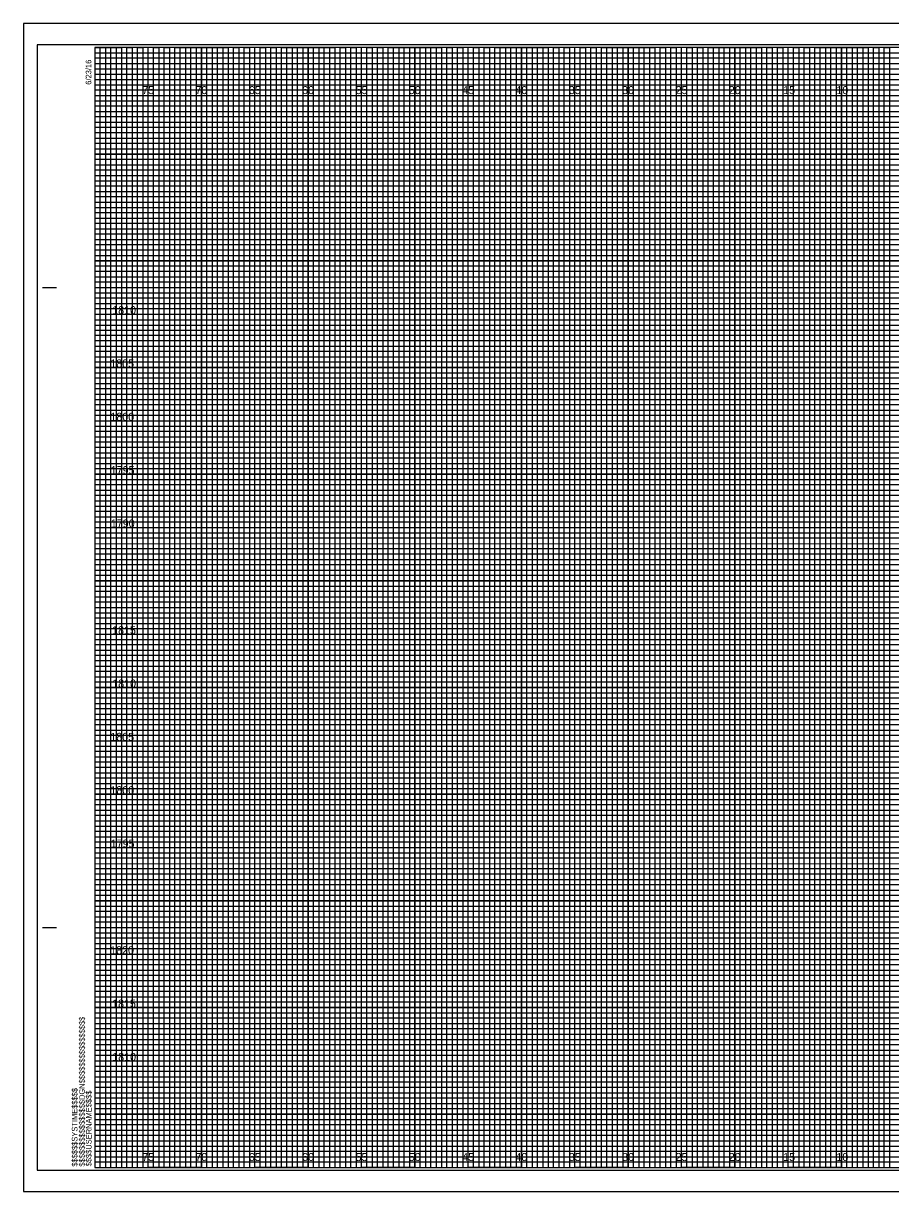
# Model space of a CAD drawing. Extents: x -7 to 162, y -2 to 327.
# Drawn here: x -6.7 to 74.6, y -2.3 to 107.3 of the extents above; entities that cross this region are included whole.
import ezdxf

# ---------------------------------------------------------------- set-up
doc = ezdxf.new("R2010")
doc.units = 0
for name, color, linetype in [('Raster_Level_0', 7, 'Continuous'), ('Scratch_Level_3', 7, 'Continuous'), ('Sheet Cross Section CELL', 7, 'Continuous'), ('Sheet Cross Section Grid Major CELL', 7, 'Continuous'), ('Sheet Cross Section Grid Middle CELL', 7, 'Continuous'), ('Sheet Cross Section Grid Minor 1 CELL', 7, 'Continuous'), ('Sheet Cross Section Grid Minor 2 CELL', 7, 'Continuous'), ('Sheet Cutting Line CELL', 7, 'Continuous'), ('Sheet DOT Grid CELL', 7, 'Continuous'), ('Sheet Plot Border Inside CELL', 7, 'Continuous'), ('Sheet Plot Border Outside CELL', 7, 'Continuous')]:
    doc.layers.add(name, color=color, linetype=linetype)

msp = doc.modelspace()

# ---------------------------------------------------------------- linework, layer by layer
at = {"layer": 'Sheet Cross Section CELL'}
for p, q in [((-4.9, 82.5), (-3.65, 82.5)), ((-4.85, 82.5), (-3.6, 82.5)), ((-4.9, 22.5), (-3.65, 22.5)), ((-4.85, 22.5), (-3.6, 22.5)), ((0, 0), (0, 0)), ((0, 0), (0, 0)), ((0, 0), (0, 0)), ((0, 0), (0, 0)), ((0, 0), (0, 0)), ((0, 0), (0, 0)), ((0, 0), (0, 0))]:
    msp.add_line(p, q, dxfattribs=at)
msp.add_lwpolyline([(160, 105), (0, 105), (0, 0), (160, 0)], close=True, dxfattribs=at)
at = {"layer": 'Sheet Cross Section Grid Major CELL'}
for p, q in [((5, 105), (0, 105)), ((5, 0), (5, 105)), ((15, 105), (10, 105)), ((10, 105), (10, 0)), ((15, 0), (15, 105)), ((25, 105), (20, 105)), ((20, 105), (20, 0)), ((25, 0), (25, 105)), ((35, 105), (30, 105)), ((30, 105), (30, 0)), ((35, 0), (35, 105)), ((45, 105), (40, 105)), ((40, 105), (40, 0)), ((45, 0), (45, 105)), ((55, 105), (50, 105)), ((50, 105), (50, 0)), ((55, 0), (55, 105)), ((65, 105), (60, 105)), ((60, 105), (60, 0)), ((65, 0), (65, 105)), ((75, 105), (70, 105)), ((70, 105), (70, 0)), ((10, 0), (5, 0)), ((20, 0), (15, 0)), ((30, 0), (25, 0)), ((40, 0), (35, 0)), ((50, 0), (45, 0)), ((60, 0), (55, 0)), ((70, 0), (65, 0))]:
    msp.add_line(p, q, dxfattribs=at)
for points in [[(0, 100), (160, 100), (160, 95), (0, 95)], [(0, 90), (160, 90), (160, 85), (0, 85)], [(0, 80), (160, 80), (160, 75), (0, 75)], [(0, 70), (160, 70), (160, 65), (0, 65)], [(0, 60), (160, 60), (160, 55), (0, 55)], [(0, 50), (160, 50), (160, 45), (0, 45)], [(0, 40), (160, 40), (160, 35), (0, 35)], [(0, 30), (160, 30), (160, 25), (0, 25)], [(0, 20), (160, 20), (160, 15), (0, 15)], [(0, 10), (160, 10), (160, 5), (0, 5)]]:
    msp.add_lwpolyline(points, dxfattribs=at)
at = {"layer": 'Sheet Cross Section Grid Middle CELL'}
for points in [[(0, 105), (2.5, 105), (2.5, 0), (7.5, 0), (7.5, 105), (12.5, 105), (12.5, 0), (17.5, 0), (17.5, 105), (22.5, 105), (22.5, 0), (27.5, 0), (27.5, 105), (32.5, 105), (32.5, 0), (37.5, 0), (37.5, 105), (42.5, 105), (42.5, 0), (47.5, 0), (47.5, 105), (52.5, 105), (52.5, 0), (57.5, 0), (57.5, 105), (62.5, 105), (62.5, 0), (67.5, 0), (67.5, 105), (72.5, 105), (72.5, 0), (77.5, 0)], [(0, 102.5), (137.5, 102.5)], [(0, 92.5), (160, 92.5), (160, 97.5), (0, 97.5)], [(0, 82.5), (160, 82.5), (160, 87.5), (0, 87.5)], [(0, 72.5), (160, 72.5), (160, 77.5), (0, 77.5)], [(0, 62.5), (160, 62.5), (160, 67.5), (0, 67.5)], [(0, 52.5), (160, 52.5), (160, 57.5), (0, 57.5)], [(0, 42.5), (160, 42.5), (160, 47.5), (0, 47.5)], [(0, 32.5), (160, 32.5), (160, 37.5), (0, 37.5)], [(0, 22.5), (160, 22.5), (160, 27.5), (0, 27.5)], [(0, 12.5), (160, 12.5), (160, 17.5), (0, 17.5)], [(0, 2.5), (160, 2.5), (160, 7.5), (0, 7.5)]]:
    msp.add_lwpolyline(points, dxfattribs=at)
at = {"layer": 'Sheet Cross Section Grid Minor 1 CELL'}
for p, q in [((0, 104.5), (130, 104.5)), ((130, 103.99), (0, 103.99)), ((0, 103.99), (0, 103.5)), ((0, 103.5), (130, 103.5)), ((130, 102.95), (0, 102.95)), ((0, 102.95), (0, 102)), ((0, 102), (160, 102))]:
    msp.add_line(p, q, dxfattribs=at)
for points in [[(0, 101.5), (135, 101.5), (160, 101.5), (160, 101), (0, 101)], [(0, 100.5), (160, 100.5), (160, 99.5), (0, 99.5)], [(0, 99), (160, 99), (160, 98.5), (0, 98.49)], [(0, 98), (160, 98), (160, 97), (0, 97)], [(0, 96.5), (160, 96.5), (160, 96), (0, 96)], [(0, 95.5), (160, 95.5), (160, 94.5), (0, 94.5)], [(0, 94), (160, 94), (160, 93.5), (0, 93.5)], [(0, 93), (160, 93), (160, 92), (0, 92)], [(0, 91.5), (160, 91.5), (160, 91), (0, 91)], [(0, 90.5), (160, 90.5), (160, 89.5), (0, 89.5)], [(0, 89), (160, 89), (160, 88.5), (0, 88.5)], [(0, 88), (160, 88), (160, 86.98), (160, 86.5), (160, 86), (0, 86)], [(0, 87), (160, 87), (160, 86.5), (0, 86.5)], [(0, 85.5), (160, 85.5), (160, 84.5), (0, 84.52)], [(0, 84.52), (160, 84.5), (160, 84), (0, 84)], [(0, 83.5), (160, 83.5), (160, 83), (0, 83)], [(0, 82), (160, 82), (160, 81.5), (0, 81.5)], [(0, 81), (160, 81), (160, 80.5), (0, 80.5)], [(-0.04, 79.45), (160, 79.45), (160, 78.94), (-0.04, 78.94)], [(0, 78.5), (160, 78.5), (160, 78), (0, 78)], [(0, 77), (160, 77), (160, 76.5), (0, 76.5)], [(0, 76), (160, 76), (160, 75.5), (0, 75.5)], [(0, 74.5), (160, 74.5), (160, 74), (0, 74)], [(0, 73.5), (160, 73.5), (160, 73), (0, 73)], [(0, 72), (160, 72), (160, 71.5), (0, 71.5)], [(0, 71), (160, 71), (160, 70.5), (0, 70.5)], [(0, 69.5), (160, 69.5), (160, 68.99), (0, 69)], [(0, 68.5), (160, 68.5), (160, 68), (0, 68)], [(0, 67), (160, 67), (160, 66.5), (0, 66.5)], [(0, 66), (160, 66), (160, 65.5), (0, 65.5)], [(0, 64.5), (160, 64.5), (160, 64), (0, 64)], [(0, 63.5), (160, 63.5), (160, 63), (0, 63)], [(0, 62), (160, 62), (160, 61.5), (0, 61.5)], [(0, 61), (160, 61), (160, 60.5), (0, 60.5)], [(0, 59.5), (160, 59.5), (160, 59), (0, 59)], [(0, 58.5), (160.03, 58.45), (160, 58), (0, 58)], [(0, 57), (160, 57), (160, 56.5), (0, 56.5)], [(0, 56), (160, 56), (160, 55.5), (0, 55.5)], [(0, 54.5), (160, 54.5), (160, 54), (0, 54)], [(0, 53.5), (160, 53.5), (160, 53), (0, 53)], [(0, 52), (160, 52), (160, 51.5), (0, 51.5)], [(0, 51), (160, 51), (160, 50.5), (0, 50.5)], [(0, 49.5), (160, 49.5), (160, 49), (0, 49)], [(0, 48.5), (160, 48.5), (160, 48), (0, 48)], [(0, 47), (160, 47), (160, 46.5), (0, 46.5)], [(0, 46), (160, 46), (160, 45.5), (0, 45.5)], [(0, 44.5), (160, 44.5), (160, 44), (0, 44)], [(0, 43.5), (160, 43.5), (160, 43), (0, 43)], [(0, 42), (160, 42), (160, 41.5), (0, 41.5)], [(0, 41), (160, 41), (160, 40.5), (0, 40.5)], [(0, 39.5), (160, 39.5), (160, 38.99), (0, 39)], [(0, 38.5), (160, 38.5), (160, 38), (0, 38)], [(0, 37), (160, 37), (160, 36.5), (0, 36.5)], [(0, 36), (160, 36), (160, 35.5), (0, 35.5)], [(0, 34.5), (160, 34.5), (160, 34), (0, 34)], [(0, 33.5), (160, 33.5), (160, 33), (0, 33)], [(0, 32), (160, 32), (160, 31.5), (0, 31.5)], [(0, 31), (160, 31), (160, 30.5), (0, 30.5)], [(0, 29.5), (160, 29.5), (160, 29), (0, 29)], [(0, 28.5), (160.03, 28.46), (160, 28), (0, 28)], [(0, 27), (160, 27), (160, 26.5), (0, 26.5)], [(0, 26), (160, 26), (160, 25.5), (0, 25.5)], [(0, 24.5), (160, 24.5), (160, 24), (0, 24)], [(0, 23.5), (160, 23.5), (160, 23), (0, 23)], [(0, 22), (160, 22), (160, 21.5), (0, 21.5)], [(0, 21), (160, 21), (160, 20.5), (0, 20.5)], [(0, 19.5), (160, 19.5), (160, 19), (0, 19)], [(0, 18.5), (160, 18.5), (160, 18), (0, 18)], [(0, 17), (160, 17), (160, 16.5), (0, 16.5)], [(0, 16), (160, 16), (160, 15.5), (0, 15.5)], [(0, 14.5), (160, 14.5), (160, 14), (0, 14)], [(0, 13.5), (160, 13.5), (160, 13), (0, 13)], [(0, 12), (160, 12), (160, 11.5), (0, 11.5)], [(0, 11), (160, 11), (160, 10.5), (0, 10.5)], [(0, 9.5), (160, 9.5), (160, 9), (0, 9)], [(0, 8.5), (160, 8.5), (160, 8), (0, 8)], [(0, 7), (160, 7), (160, 6.5), (0, 6.5)], [(0, 6), (160, 6), (160, 5.5), (0, 5.5)], [(0, 4.5), (160, 4.5), (160, 4), (0, 4)], [(0, 3.5), (160, 3.5), (160, 3), (0, 3)], [(0, 2), (160, 2), (160, 1.5), (0, 1.5)], [(0, 1), (160, 1), (160, 0.5), (0, 0.5)]]:
    msp.add_lwpolyline(points, dxfattribs=at)
at = {"layer": 'Sheet Cross Section Grid Minor 2 CELL'}
for points in [[(0, 0), (0.5, 0), (0.5, 105), (1, 105), (1, 0)], [(1, 0), (1.5, 0), (1.5, 105), (2, 105), (2, 0)], [(2.5, 0), (3, 0), (3, 105), (3.5, 105), (3.5, 0)], [(3.5, 0), (4, 0), (4, 105), (4.5, 105), (4.5, 0)], [(5, 0), (5.5, 0), (5.5, 105), (6, 105), (6, 0)], [(6, 0), (6.5, 0), (6.5, 105), (7, 105), (7, 0)], [(7.5, 0), (8, 0), (8, 105), (8.5, 105), (8.5, 0)], [(8.5, 0), (9, 0), (9, 105), (9.5, 105), (9.5, 0)], [(10, 0), (10.5, 0), (10.5, 105), (11, 105), (11, 0)], [(11, 0), (11.5, 0), (11.5, 105), (12, 105), (12, 0)], [(12.5, 0), (13, 0), (13, 105), (13.5, 105), (13.5, 0)], [(13.5, 0), (14, 0), (14, 105), (14.5, 105), (14.5, 0)], [(15, 0), (15.5, 0), (15.5, 105), (16, 105), (16, 0)], [(16, 0), (16.5, 0), (16.5, 105), (17, 105), (17, 0)], [(17.5, 0), (18, 0), (18, 105), (18.5, 105), (18.5, 0)], [(18.5, 0), (19, 0), (19, 105), (19.5, 105), (19.5, 0)], [(20, 0), (20.5, 0), (20.5, 105), (21, 105), (21, 0)], [(21, 0), (21.5, 0), (21.5, 105), (22, 105), (22, 0)], [(22.5, 0), (23, 0), (23, 105), (23.5, 105), (23.5, 0)], [(23.5, 0), (24, 0), (24, 105), (24.5, 105), (24.5, 0)], [(25, 0), (25.5, 0), (25.5, 105), (26, 105), (26, 0)], [(26, 0), (26.5, 0), (26.5, 105), (27, 105), (27, 0)], [(27.5, 0), (28, 0), (28, 105), (28.5, 105), (28.5, 0)], [(28.5, 0), (29, 0), (29, 105), (29.5, 105), (29.5, 0)], [(30, 0), (30.5, 0), (30.5, 105), (31, 105), (31, 0)], [(31, 0), (31.5, 0), (31.5, 105), (32, 105), (32, 0)], [(32.5, 0), (33, 0), (33, 105), (33.5, 105), (33.5, 0)], [(33.5, 0), (34, 0), (34, 105), (34.5, 105), (34.5, 0)], [(35, 0), (35.5, 0), (35.5, 105), (36, 105), (36, 0)], [(36, 0), (36.5, 0), (36.5, 105), (37, 105), (37, 0)], [(37.5, 0), (38, 0), (38, 105), (38.5, 105), (38.5, 0)], [(38.5, 0), (39, 0), (39, 105), (39.5, 105), (39.5, 0)], [(40, 0), (40.5, 0), (40.5, 105), (41, 105), (41, 0)], [(41, 0), (41.5, 0), (41.5, 105), (42, 105), (42, 0)], [(42.5, 0), (43, 0), (43, 105), (43.5, 105), (43.5, 0)], [(43.5, 0), (44, 0), (44, 105), (44.5, 105), (44.5, 0)], [(45, 0), (45.5, 0), (45.5, 105), (46, 105), (46, 0)], [(46, 0), (46.5, 0), (46.5, 105), (47, 105), (47, 0)], [(47.5, 0), (48, 0), (48, 105), (48.5, 105), (48.5, 0)], [(48.5, 0), (49, 0), (49, 105), (49.5, 105), (49.5, 0)], [(50, 0), (50.5, 0), (50.5, 105), (51, 105), (51, 0)], [(51, 0), (51.5, 0), (51.5, 105), (52, 105), (52, 0)], [(52.5, 0), (53, 0), (53, 105), (53.5, 105), (53.5, 0)], [(53.5, 0), (54, 0), (54, 105), (54.5, 105), (54.5, 0)], [(55, 0), (55.5, 0), (55.5, 105), (56, 105), (56, 0)], [(56, 0), (56.5, 0), (56.5, 105), (57, 105), (57, 0)], [(57.5, 0), (58, 0), (58, 105), (58.5, 105), (58.5, 0)], [(58.5, 0), (59, 0), (59, 105), (59.5, 105), (59.5, 0)], [(60, 0), (60.5, 0), (60.5, 105), (61, 105), (61, 0)], [(61, 0), (61.5, 0), (61.5, 105), (62, 105), (62, 0)], [(62.5, 0), (63, 0), (63, 105), (63.5, 105), (63.5, 0)], [(63.5, 0), (64, 0), (64, 105), (64.5, 105), (64.5, 0)], [(65, 0), (65.5, 0), (65.5, 105), (66, 105), (66, 0)], [(66, 0), (66.5, 0), (66.5, 105), (67, 105), (67, 0)], [(67.5, 0), (68, 0), (68, 105), (68.5, 105), (68.5, 0)], [(68.5, 0), (69, 0), (69, 105), (69.5, 105), (69.5, 0)], [(70, 0), (70.5, 0), (70.5, 105), (71, 105), (71, 0)], [(71, 0), (71.5, 0), (71.5, 105), (72, 105), (72, 0)], [(72.5, 0), (73, 0), (73, 105), (73.5, 105), (73.5, 0)], [(73.5, 0), (74, 0), (74, 105), (74.5, 105), (74.5, 0)]]:
    msp.add_lwpolyline(points, dxfattribs=at)
at = {"layer": 'Sheet Cutting Line CELL'}
for p, q in [((161.65, 107.25), (-6.7, 107.25)), ((-6.7, 107.25), (-6.7, -2.25)), ((-6.7, -2.25), (161.65, -2.25))]:
    msp.add_line(p, q, dxfattribs=at)
at = {"layer": 'Sheet DOT Grid CELL'}
for p, q in [((5, 0), (5, 105)), ((10, 0), (10, 105)), ((15, 0), (15, 105)), ((20, 0), (20, 105)), ((25, 0), (25, 105)), ((30, 0), (30, 105)), ((35, 0), (35, 105)), ((40, 0), (40, 105)), ((45, 0), (45, 105)), ((50, 0), (50, 105)), ((55, 0), (55, 105)), ((60, 0), (60, 105)), ((65, 0), (65, 105)), ((70, 0), (70, 105)), ((0, 100), (160, 100)), ((0, 95), (160, 95)), ((0, 90), (160, 90)), ((0, 85), (160, 85)), ((0, 80), (160, 80)), ((0, 75), (160, 75)), ((0, 70), (160, 70)), ((0, 65), (160, 65)), ((0, 60), (160, 60)), ((0, 55), (160, 55)), ((0, 50), (160, 50)), ((0, 45), (160, 45)), ((0, 40), (160, 40)), ((0, 35), (160, 35)), ((0, 30), (160, 30)), ((0, 25), (160, 25)), ((0, 20), (160, 20)), ((0, 15), (160, 15)), ((0, 10), (160, 10)), ((0, 5), (160, 5))]:
    msp.add_line(p, q, dxfattribs=at)
at = {"layer": 'Sheet Plot Border Inside CELL'}
msp.add_lwpolyline([(-5.4, -0.25), (161.2, -0.25), (161.2, 105.25), (-5.4, 105.25)], close=True, dxfattribs=at)
at = {"layer": 'Sheet Plot Border Outside CELL'}
msp.add_lwpolyline([(-6.7, -2.25), (161.65, -2.25), (161.65, 107.25), (-6.7, 107.25)], close=True, dxfattribs=at)

# ---------------------------------------------------------------- texts
at = {"layer": 'Raster_Level_0'}
for s, p in [('75', (4.44, 100.62)), ('70', (9.43, 100.62)), ('65', (14.44, 100.62)), ('60', (19.43, 100.62)), ('55', (24.44, 100.62)), ('50', (29.43, 100.62)), ('45', (34.44, 100.62)), ('40', (39.43, 100.62)), ('35', (44.44, 100.62)), ('30', (49.43, 100.62)), ('25', (54.44, 100.62)), ('20', (59.43, 100.62)), ('15', (64.53, 100.62)), ('10', (69.52, 100.62)), ('75', (4.44, 0.62)), ('70', (9.43, 0.62)), ('65', (14.44, 0.62)), ('60', (19.43, 0.62)), ('55', (24.44, 0.62)), ('50', (29.43, 0.62)), ('45', (34.44, 0.62)), ('40', (39.43, 0.62)), ('35', (44.44, 0.62)), ('30', (49.43, 0.62)), ('25', (54.44, 0.62)), ('20', (59.43, 0.62)), ('15', (64.53, 0.62)), ('10', (69.52, 0.62))]:
    msp.add_text(s, height=0.75, dxfattribs=at).set_placement(p)
at = {"layer": 'Scratch_Level_3'}
for s, p in [('1810', (1.63, 80)), ('1805', (1.45, 75)), ('1800', (1.46, 70)), ('1795', (1.49, 65)), ('1790', (1.5, 60)), ('1815', (1.62, 50)), ('1810', (1.63, 45)), ('1805', (1.45, 40)), ('1800', (1.46, 35)), ('1795', (1.49, 30)), ('1820', (1.44, 20)), ('1815', (1.62, 15)), ('1810', (1.63, 10))]:
    msp.add_text(s, height=0.75, dxfattribs=at).set_placement(p)
at = {"layer": 'Sheet Cross Section CELL'}
for s, p in [('6/23/16', (-0.33, 101.5)), ('$$$$$$$$$$$$$$$$DGN$$$$$$$$$$$$$$$$', (-0.94, 0.09)), ('$$$$$$SYSTIME$$$$$', (-1.63, 0.09)), ('$$$$USERNAME$$$$', (-0.31, 0.12))]:
    msp.add_text(s, height=0.525, rotation=90, dxfattribs=at).set_placement(p)

doc.saveas('drawing.dxf')
